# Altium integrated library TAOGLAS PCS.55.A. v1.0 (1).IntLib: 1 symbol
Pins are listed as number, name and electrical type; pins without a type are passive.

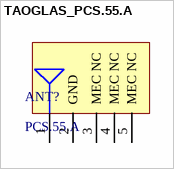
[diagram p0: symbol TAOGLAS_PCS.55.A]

## TAOGLAS_PCS.55.A
designator ANT?, comment PCS.55.A
ComponentLibStatus: Created; MFG: Taoglas; Temp_High: +85C; Temp_Low: -40C
footprint TAOGLAS_PCS.55.A
pins: 1 RF FEED, 2 GND, 3 MEC NC, 4 MEC NC, 5 MEC NC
